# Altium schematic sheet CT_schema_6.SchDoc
size 277 x 170 mm
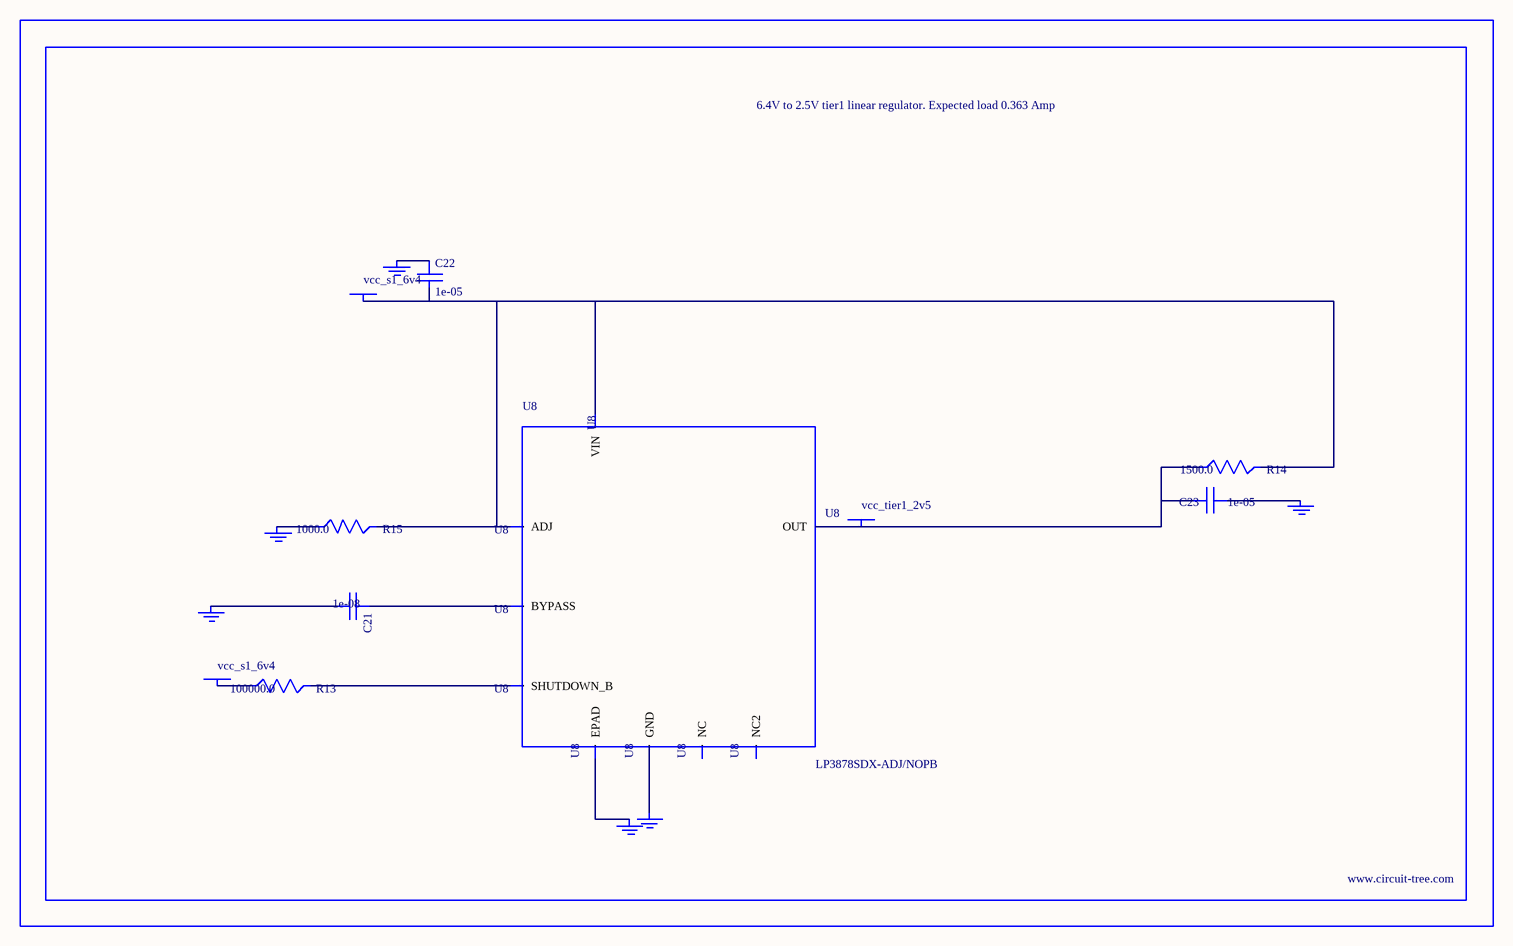
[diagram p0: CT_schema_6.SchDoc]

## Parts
BORDER5  (no value)
C21  1e-08  [C0402]
C22  1e-05  [C1206]
C23  1e-05  [C1210]
GND_INSTANCE_5_0  (no value)
GND_INSTANCE_5_1  (no value)
GND_INSTANCE_5_2  (no value)
GND_INSTANCE_5_3  (no value)
GND_INSTANCE_5_4  (no value)
GND_INSTANCE_5_5  (no value)
POWER_INSTANCE_5_0  vcc_s1_6v4
POWER_INSTANCE_5_1  vcc_s1_6v4
POWER_INSTANCE_5_2  vcc_tier1_2v5
R13  100000.0  [R0603]
R14  1500.0  [R0603]
R15  1000.0  [R0603]
U8  LP3878SDX-ADJ/NOPB  [WSON-8]

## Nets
NetC21_1: C21.1 U8.1(BYPASS)
NetC21_2: C21.2 GND_INSTANCE_5_0.0(GND)
NetC22_1: C22.1 GND_INSTANCE_5_1.0(GND)
NetC22_2: C22.2 POWER_INSTANCE_5_0.0(PWR) R14.2 R15.2 U8.4(VIN) U8.6(ADJ)
NetC23_1: C23.1 GND_INSTANCE_5_2.0(GND)
NetC23_2: C23.2 POWER_INSTANCE_5_2.0(PWR) R14.1 U8.5(OUT)
NetGND_INSTANCE_5_3_0: GND_INSTANCE_5_3.0(GND) R15.1
NetGND_INSTANCE_5_4_0: GND_INSTANCE_5_4.0(GND) U8.PAD(EPAD)
NetGND_INSTANCE_5_5_0: GND_INSTANCE_5_5.0(GND) U8.3(GND)
NetPOWER_INSTANCE_5_1_0: POWER_INSTANCE_5_1.0(PWR) R13.1
NetR13_2: R13.2 U8.8(SHUTDOWN_B)

Not connected (* = marked no-connect by the designer): U8 2(NC) 7(NC2)

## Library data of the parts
BORDER5 = BORDER_PAGE5
C21 = C0402C103K3RAC
C22 = C1206C106K3RACTU
C23 = GRM32DR61E106MA12L
GND_INSTANCE_5_0-GND_INSTANCE_5_5 = GND
POWER_INSTANCE_5_0-POWER_INSTANCE_5_2 = PWR
R13 = RC0603JR-07100KL
R14 = RC0603JR-071K5L
R15 = RC0603JR-071KL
